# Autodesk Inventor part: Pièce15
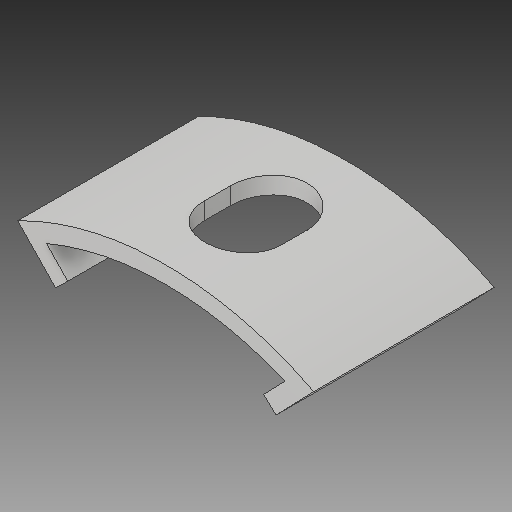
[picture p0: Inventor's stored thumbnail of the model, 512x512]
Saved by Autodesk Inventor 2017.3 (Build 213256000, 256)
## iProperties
Created: 2007-11
Part Number: Pièce15
Material: Générique
Document SubType Name: Modeling
Designer: ficho
Density: 1 g/cm^3
Appearance: Par défaut
Author: ficho
Sending System: SolidWorks 2009
Last Author: christophe
Last Saved: 2011-02-10
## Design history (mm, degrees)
feature "Enlèv. mat.-Extru.1"
node "Solide1"
